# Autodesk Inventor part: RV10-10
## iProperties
Created: 2006-07
Part Number: RV10-10
Document SubType Name: Modeling
Designer: Administrator
Author: Administrator
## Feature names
1. Revolution1
2. Extrusion1
3. Loft1
4. Fillet1
5. Revolution2
